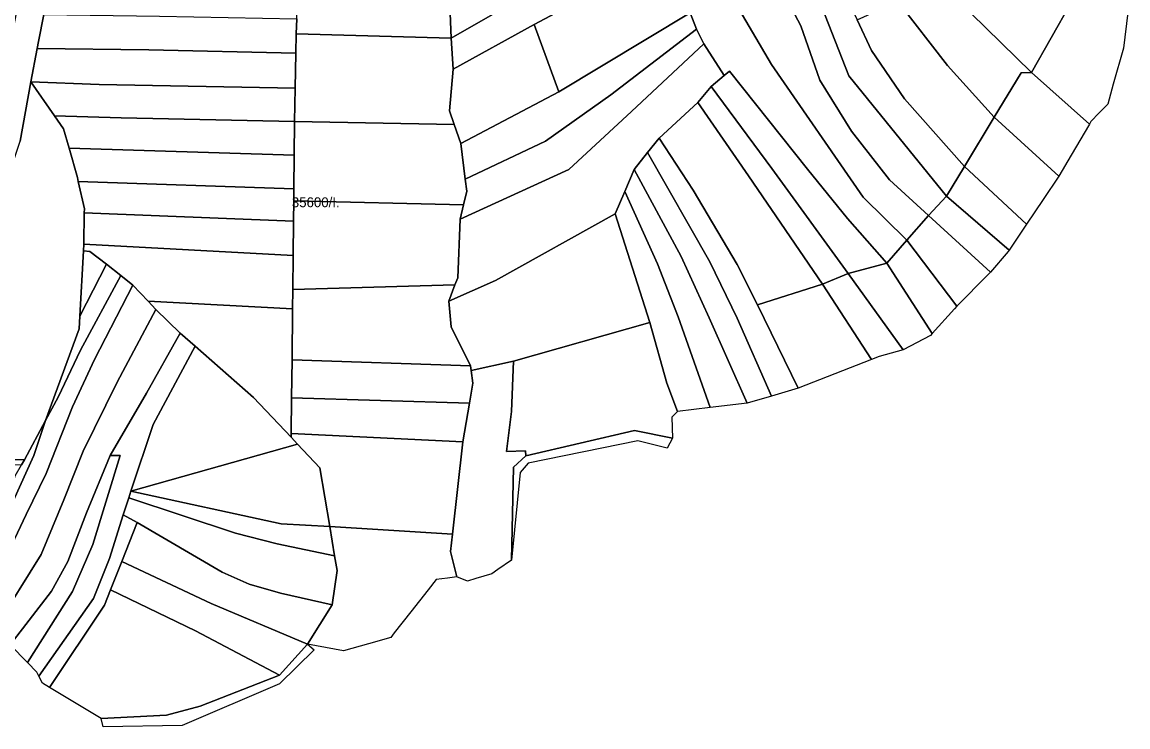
# Model space of a CAD drawing. Extents: x -537068 to -534056, y -1176840 to -1172401.
# Drawn here: x -534697 to -534139, y -1175857 to -1175501 of the extents above; entities that cross this region are included whole.
import ezdxf

# ---------------------------------------------------------------- set-up
doc = ezdxf.new("R2010")
doc.units = 0
for name, color, linetype in [('95610013', 7, 'Continuous'), ('95630013', 7, 'Continuous'), ('95640013', 7, 'Continuous'), ('95660013', 7, 'Continuous')]:
    doc.layers.add(name, color=color, linetype=linetype)

msp = doc.modelspace()

# ---------------------------------------------------------------- linework, layer by layer
at = {"layer": '95610013'}
for points in [[(-534309.1, -1175429), (-534275.74, -1175499.62), (-534268.45, -1175515.14), (-534251.84, -1175539.54), (-534221.44, -1175573.84), (-534230.56, -1175588.8), (-534279.95, -1175527.98), (-534291.85, -1175497.5), (-534332.21, -1175416.26), (-534322.8, -1175410), (-534316.7, -1175408.3)], [(-534291.85, -1175497.5), (-534279.95, -1175527.98), (-534230.56, -1175588.8), (-534239.67, -1175598.58), (-534259.46, -1175580.46), (-534278.62, -1175555.92), (-534294.61, -1175530.11), (-534304.14, -1175502.62), (-534318.85, -1175474.84), (-534348.4, -1175423.92), (-534341.07, -1175419), (-534338.93, -1175418.34), (-534332.21, -1175416.26)], [(-534318.85, -1175474.84), (-534304.14, -1175502.62), (-534294.61, -1175530.11), (-534278.62, -1175555.92), (-534259.46, -1175580.46), (-534239.67, -1175598.58), (-534250.58, -1175610.99), (-534272.76, -1175589.26), (-534319.03, -1175522.16), (-534368.68, -1175437.51), (-534354.54, -1175428.03), (-534348.4, -1175423.92)], [(-534280.66, -1175600.07), (-534300.74, -1175575.06), (-534340.21, -1175525.59), (-534342.87, -1175527.85), (-534353.09, -1175511.77), (-534356.78, -1175504.45), (-534360.05, -1175496.11), (-534370.47, -1175469.58), (-534373.24, -1175463.28), (-534375.65, -1175457.61), (-534381.21, -1175444.57), (-534368.68, -1175437.51), (-534319.03, -1175522.16), (-534272.76, -1175589.26), (-534250.58, -1175610.99), (-534260.77, -1175622.59)], [(-534418.13, -1175449.79), (-534375.65, -1175457.61), (-534373.24, -1175463.28), (-534413.18, -1175467.24), (-534442.21, -1175486.64), (-534480.69, -1175508.98), (-534481.43, -1175492.13), (-534472.95, -1175480.84), (-534448.92, -1175472.59), (-534443.51, -1175464)], [(-534370.47, -1175469.58), (-534387.33, -1175478.81), (-534410.12, -1175483.84), (-534420.15, -1175492.09), (-534438.86, -1175502.02), (-534479.78, -1175524.55), (-534480.69, -1175508.98), (-534442.21, -1175486.64), (-534413.18, -1175467.24), (-534373.24, -1175463.28)], [(-534558.97, -1175506.8), (-534558.7, -1175499.14), (-534558.16, -1175483.43), (-534557.66, -1175468.79), (-534469.54, -1175469.05), (-534472.95, -1175480.84), (-534481.43, -1175492.13), (-534480.69, -1175508.98)], [(-534438.86, -1175502.02), (-534420.15, -1175492.09), (-534410.12, -1175483.84), (-534387.33, -1175478.81), (-534370.47, -1175469.58), (-534360.05, -1175496.11), (-534426.44, -1175536.12)], [(-534187.7, -1175526.35), (-534192.93, -1175526.44), (-534206.45, -1175548.92), (-534230.13, -1175522.7), (-534255.21, -1175490.47), (-534233.61, -1175481.15)], [(-534167.8, -1175491.2), (-534187.7, -1175526.35), (-534233.61, -1175481.15)], [(-534230.13, -1175522.7), (-534206.45, -1175548.92), (-534221.44, -1175573.84), (-534251.84, -1175539.54), (-534268.45, -1175515.14), (-534275.74, -1175499.62), (-534255.21, -1175490.47)], [(-534153.54, -1175546.74), (-534157.7, -1175551.1), (-534158.46, -1175552.4), (-534187.7, -1175526.35), (-534167.8, -1175491.2), (-534139, -1175495.9), (-534141.2, -1175514), (-534146.36, -1175532.18), (-534149.2, -1175542.2)], [(-534628.15, -1175497.81), (-534558.7, -1175499.14), (-534558.97, -1175506.8), (-534559.18, -1175516.47), (-534633.48, -1175514.87), (-534689.8, -1175514.09), (-534689.12, -1175510.64), (-534686.46, -1175497.02)], [(-534360.05, -1175496.11), (-534356.78, -1175504.45), (-534400.15, -1175537.48), (-534433.16, -1175560.94), (-534473.65, -1175580.18), (-534475.88, -1175562.23), (-534426.44, -1175536.12)], [(-534479.78, -1175524.55), (-534438.86, -1175502.02), (-534426.44, -1175536.12), (-534475.88, -1175562.23), (-534479.28, -1175552.53), (-534481.69, -1175545.66)], [(-534479.28, -1175552.53), (-534559.92, -1175550.98), (-534559.56, -1175534.15), (-534559.18, -1175516.47), (-534558.97, -1175506.8), (-534480.69, -1175508.98), (-534479.78, -1175524.55), (-534481.69, -1175545.66)], [(-534476.22, -1175600.36), (-534474.53, -1175593.19), (-534472.89, -1175586.26), (-534473.65, -1175580.18), (-534433.16, -1175560.94), (-534400.15, -1175537.48), (-534356.78, -1175504.45), (-534353.09, -1175511.77), (-534389.63, -1175546.06), (-534421.28, -1175575.21)], [(-534689.8, -1175514.09), (-534633.48, -1175514.87), (-534559.18, -1175516.47), (-534559.56, -1175534.15), (-534658.46, -1175532.4), (-534693.13, -1175530.98)], [(-534349.41, -1175533.39), (-534356.26, -1175541.48), (-534375.8, -1175559.41), (-534381.53, -1175566.7), (-534388.31, -1175575.32), (-534393.11, -1175586.43), (-534397.98, -1175597.72), (-534458.36, -1175631.34), (-534481.97, -1175641.83), (-534478.84, -1175633.55), (-534477.48, -1175629.96), (-534476.22, -1175600.36), (-534421.28, -1175575.21), (-534389.63, -1175546.06), (-534353.09, -1175511.77), (-534342.87, -1175527.85)], [(-534349.41, -1175533.39), (-534342.87, -1175527.85), (-534340.21, -1175525.59), (-534300.74, -1175575.06), (-534280.66, -1175600.07), (-534260.77, -1175622.59), (-534280.32, -1175627.86), (-534318.8, -1175574.83)], [(-534750.52, -1175688.37), (-534735.93, -1175659.99), (-534729.02, -1175644.76), (-534723.65, -1175632.94), (-534712.33, -1175602.64), (-534698.48, -1175560.95), (-534693.13, -1175530.98), (-534681.17, -1175548.21), (-534676.6, -1175554.8), (-534673.77, -1175564.57), (-534669.5, -1175579.3), (-534669.07, -1175581.27), (-534666, -1175595.2), (-534666.04, -1175597.21), (-534666.34, -1175612.96), (-534666.4, -1175616.4), (-534668.32, -1175649.36), (-534668.7, -1175655.8), (-534685.7, -1175702.1), (-534696.3, -1175721.9), (-534728.7, -1175721.7), (-534765.6, -1175721.8), (-534770.72, -1175721.95)], [(-534658.46, -1175532.4), (-534559.56, -1175534.15), (-534559.92, -1175550.98), (-534647.42, -1175549.16), (-534681.17, -1175548.21), (-534693.13, -1175530.98)], [(-534187.7, -1175526.35), (-534158.46, -1175552.4), (-534167.66, -1175568.11), (-534173.8, -1175578.6), (-534206.45, -1175548.92), (-534192.93, -1175526.44)], [(-534318.8, -1175574.83), (-534280.32, -1175627.86), (-534293.28, -1175633.25), (-534330.65, -1175578.48), (-534356.26, -1175541.48), (-534349.41, -1175533.39)], [(-534358.58, -1175585.77), (-534375.8, -1175559.41), (-534356.26, -1175541.48), (-534330.65, -1175578.48), (-534293.28, -1175633.25), (-534326.14, -1175643.61), (-534336.29, -1175623.32)], [(-534647.42, -1175549.16), (-534559.92, -1175550.98), (-534560.07, -1175568.02), (-534673.77, -1175564.57), (-534676.6, -1175554.8), (-534681.17, -1175548.21)], [(-534475.88, -1175562.23), (-534473.65, -1175580.18), (-534472.89, -1175586.26), (-534474.53, -1175593.19), (-534560.27, -1175591.13), (-534560.22, -1175585.07), (-534560.07, -1175568.02), (-534559.92, -1175550.98), (-534479.28, -1175552.53)], [(-534206.45, -1175548.92), (-534173.8, -1175578.6), (-534181.8, -1175590.5), (-534190.18, -1175602.95), (-534221.44, -1175573.84)], [(-534350.08, -1175621.95), (-534381.53, -1175566.7), (-534375.8, -1175559.41), (-534358.58, -1175585.77), (-534336.29, -1175623.32), (-534326.14, -1175643.61), (-534305.6, -1175685.8), (-534318.93, -1175689.74), (-534336.26, -1175650.45)], [(-534669.5, -1175579.3), (-534673.77, -1175564.57), (-534560.07, -1175568.02), (-534560.22, -1175585.07), (-534669.07, -1175581.27)], [(-534388.31, -1175575.32), (-534381.53, -1175566.7), (-534350.08, -1175621.95), (-534336.26, -1175650.45), (-534318.93, -1175689.74), (-534331.3, -1175693.4), (-534350.54, -1175650.22), (-534364.59, -1175619.16)], [(-534388.31, -1175575.32), (-534364.59, -1175619.16), (-534350.54, -1175650.22), (-534331.3, -1175693.4), (-534349.97, -1175695.58), (-534366.16, -1175649.8), (-534376.61, -1175622.9), (-534393.11, -1175586.43)], [(-534198.95, -1175615.99), (-534230.56, -1175588.8), (-534221.44, -1175573.84), (-534190.18, -1175602.95)], [(-534560.22, -1175585.07), (-534560.27, -1175591.13), (-534560.38, -1175601.33), (-534666.04, -1175597.21), (-534666, -1175595.2), (-534669.07, -1175581.27)], [(-534349.97, -1175695.58), (-534366.4, -1175697.5), (-534371.8, -1175683.25), (-534380.43, -1175652.52), (-534397.98, -1175597.72), (-534393.11, -1175586.43), (-534376.61, -1175622.9), (-534366.16, -1175649.8)], [(-534560.27, -1175591.13), (-534474.53, -1175593.19), (-534476.22, -1175600.36), (-534477.48, -1175629.96), (-534478.84, -1175633.55), (-534560.75, -1175635.86), (-534560.57, -1175618.77), (-534560.38, -1175601.33)], [(-534199.5, -1175616.8), (-534208.45, -1175627.18), (-534239.67, -1175598.58), (-534230.56, -1175588.8), (-534198.95, -1175615.99)], [(-534666.04, -1175597.21), (-534560.38, -1175601.33), (-534560.57, -1175618.77), (-534666.34, -1175612.96)], [(-534470.92, -1175674.4), (-534480.78, -1175654.79), (-534481.97, -1175641.83), (-534458.36, -1175631.34), (-534397.98, -1175597.72), (-534380.43, -1175652.52), (-534449.28, -1175672.05), (-534470.61, -1175676.91)], [(-534250.58, -1175610.99), (-534239.67, -1175598.58), (-534208.45, -1175627.18), (-534209.5, -1175628.4), (-534225.33, -1175644.42)], [(-534663.21, -1175616.65), (-534666.4, -1175616.4), (-534666.34, -1175612.96), (-534560.57, -1175618.77), (-534560.75, -1175635.86), (-534560.86, -1175645.69), (-534633.82, -1175641.88), (-534641.45, -1175633.76), (-534647.62, -1175628.85), (-534654.76, -1175623.11)], [(-534260.77, -1175622.59), (-534250.58, -1175610.99), (-534225.33, -1175644.42), (-534226.6, -1175645.7), (-534237.82, -1175658.12)], [(-534654.76, -1175623.11), (-534668.32, -1175649.36), (-534666.4, -1175616.4), (-534663.21, -1175616.65)], [(-534647.62, -1175628.85), (-534668, -1175666.49), (-534679.16, -1175690.37), (-534685.7, -1175702.1), (-534668.7, -1175655.8), (-534668.32, -1175649.36), (-534654.76, -1175623.11)], [(-534260.77, -1175622.59), (-534237.82, -1175658.12), (-534238.7, -1175659.1), (-534252.5, -1175666.4), (-534280.32, -1175627.86)], [(-534641.45, -1175633.76), (-534660.89, -1175671.25), (-534671.97, -1175695.23), (-534685.28, -1175728.86), (-534695.38, -1175749.53), (-534708.73, -1175777.45), (-534719.09, -1175796.69), (-534725.5, -1175788.39), (-534715.51, -1175771.26), (-534701.94, -1175742.9), (-534691.51, -1175719.79), (-534685.7, -1175702.1), (-534679.16, -1175690.37), (-534668, -1175666.49), (-534647.62, -1175628.85)], [(-534293.28, -1175633.25), (-534280.32, -1175627.86), (-534252.5, -1175666.4), (-534264.6, -1175669.8), (-534268.4, -1175671.28)], [(-534666.58, -1175717.56), (-534676.38, -1175742.12), (-534687.85, -1175769.72), (-534711.11, -1175806.77), (-534712.9, -1175804.7), (-534719.09, -1175796.69), (-534708.73, -1175777.45), (-534695.38, -1175749.53), (-534685.28, -1175728.86), (-534671.97, -1175695.23), (-534660.89, -1175671.25), (-534641.45, -1175633.76), (-534633.82, -1175641.88), (-534629.87, -1175646.08), (-534649.44, -1175682.8)], [(-534561.14, -1175671.49), (-534560.86, -1175645.69), (-534560.75, -1175635.86), (-534478.84, -1175633.55), (-534481.97, -1175641.83), (-534480.78, -1175654.79), (-534470.92, -1175674.4)], [(-534268.4, -1175671.28), (-534305.6, -1175685.8), (-534326.14, -1175643.61), (-534293.28, -1175633.25)], [(-534610.02, -1175664.58), (-534617.62, -1175657.91), (-534629.87, -1175646.08), (-534633.82, -1175641.88), (-534560.86, -1175645.69), (-534561.14, -1175671.49), (-534561.34, -1175690.6), (-534561.54, -1175708.73), (-534561.56, -1175710.6), (-534580.53, -1175690.49)], [(-534674.43, -1175773.31), (-534682.62, -1175788.25), (-534703.42, -1175815.43), (-534705.1, -1175813.7), (-534711.11, -1175806.77), (-534687.85, -1175769.72), (-534676.38, -1175742.12), (-534666.58, -1175717.56), (-534649.44, -1175682.8), (-534629.87, -1175646.08), (-534617.62, -1175657.91), (-534634.58, -1175688.25), (-534652.9, -1175719.72), (-534665, -1175748.82)], [(-534369, -1175711), (-534388.2, -1175707.2), (-534443.1, -1175719.9), (-534443.15, -1175717.42), (-534452.83, -1175717.79), (-534450.3, -1175697.57), (-534449.28, -1175672.05), (-534380.43, -1175652.52), (-534371.8, -1175683.25), (-534366.4, -1175697.5), (-534369.4, -1175700.5)], [(-534653.25, -1175771.82), (-534661.46, -1175791.95), (-534688.94, -1175831.32), (-534690, -1175829.2), (-534694.65, -1175824.42), (-534672.04, -1175788.51), (-534661.73, -1175764.74), (-534647.87, -1175719.77), (-534652.9, -1175719.72), (-534634.58, -1175688.25), (-534617.62, -1175657.91), (-534610.02, -1175664.58), (-534631.31, -1175704.11), (-534642.49, -1175737.82), (-534643.6, -1175741.18), (-534646.45, -1175749.76)], [(-534631.31, -1175704.11), (-534610.02, -1175664.58), (-534580.53, -1175690.49), (-534561.56, -1175710.6), (-534558.34, -1175714.01), (-534642.49, -1175737.82)], [(-534470.92, -1175674.4), (-534470.61, -1175676.91), (-534469.84, -1175683.23), (-534471.54, -1175693.42), (-534561.34, -1175690.6), (-534561.14, -1175671.49)], [(-534474.79, -1175712.83), (-534471.54, -1175693.42), (-534469.84, -1175683.23), (-534470.61, -1175676.91), (-534449.28, -1175672.05), (-534450.3, -1175697.57), (-534452.83, -1175717.79), (-534443.15, -1175717.42), (-534443.1, -1175719.9), (-534449.3, -1175725.6), (-534450.3, -1175772.6), (-534457.22, -1175777.42), (-534460.2, -1175779.5), (-534468.27, -1175781.97), (-534472.6, -1175783.3), (-534477.9, -1175781.1), (-534481.1, -1175768.37), (-534480.09, -1175759.48)], [(-534561.54, -1175708.73), (-534561.34, -1175690.6), (-534471.54, -1175693.42), (-534474.79, -1175712.83)], [(-534697.8, -1175724.5), (-534696.3, -1175721.9), (-534685.7, -1175702.1), (-534691.51, -1175719.79), (-534701.94, -1175742.9), (-534715.51, -1175771.26), (-534725.5, -1175788.39), (-534734.3, -1175777), (-534721.9, -1175766.7), (-534703.6, -1175742), (-534700.9, -1175730.1)], [(-534480.09, -1175759.48), (-534542.1, -1175755.58), (-534547.02, -1175726.02), (-534558.34, -1175714.01), (-534561.56, -1175710.6), (-534561.54, -1175708.73), (-534474.79, -1175712.83)], [(-534443.1, -1175719.9), (-534388.2, -1175707.2), (-534369, -1175711), (-534371.7, -1175716), (-534386.5, -1175712.3), (-534441.8, -1175723.6), (-534446, -1175728.4), (-534450.3, -1175772.6), (-534449.3, -1175725.6)], [(-534542.1, -1175755.58), (-534566.61, -1175754.34), (-534642.49, -1175737.82), (-534558.34, -1175714.01), (-534547.02, -1175726.02)], [(-534672.04, -1175788.51), (-534694.65, -1175824.42), (-534703.42, -1175815.43), (-534682.62, -1175788.25), (-534674.43, -1175773.31), (-534665, -1175748.82), (-534652.9, -1175719.72), (-534647.87, -1175719.77), (-534661.73, -1175764.74)], [(-534568.62, -1175764.4), (-534589.64, -1175759.01), (-534643.6, -1175741.18), (-534642.49, -1175737.82), (-534566.61, -1175754.34), (-534542.1, -1175755.58), (-534539.63, -1175770.42)], [(-534582.77, -1175784.86), (-534596.44, -1175778.79), (-534639.31, -1175753.57), (-534646.45, -1175749.76), (-534643.6, -1175741.18), (-534589.64, -1175759.01), (-534568.62, -1175764.4), (-534539.63, -1175770.42), (-534538.39, -1175777.85), (-534540.85, -1175795.21), (-534567.03, -1175789.29)], [(-534639.31, -1175753.57), (-534647.11, -1175773.34), (-534652.76, -1175787.67), (-534655.85, -1175795.42), (-534683.7, -1175836.92), (-534687.2, -1175834.8), (-534688.94, -1175831.32), (-534661.46, -1175791.95), (-534653.25, -1175771.82), (-534646.45, -1175749.76)], [(-534639.31, -1175753.57), (-534596.44, -1175778.79), (-534582.77, -1175784.86), (-534567.03, -1175789.29), (-534540.85, -1175795.21), (-534553.3, -1175815.1), (-534602.05, -1175794.52), (-534647.11, -1175773.34)], [(-534480.09, -1175759.48), (-534481.1, -1175768.37), (-534477.9, -1175781.1), (-534482.68, -1175781.7), (-534488.3, -1175782.4), (-534492.38, -1175787.6), (-534501.15, -1175798.77), (-534509.48, -1175809.38), (-534511.3, -1175811.7), (-534522.47, -1175814.89), (-534535.1, -1175818.5), (-534553.3, -1175815.1), (-534540.85, -1175795.21), (-534538.39, -1175777.85), (-534539.63, -1175770.42), (-534542.1, -1175755.58)], [(-534567.5, -1175830.7), (-534609.84, -1175808.4), (-534652.76, -1175787.67), (-534647.11, -1175773.34), (-534602.05, -1175794.52), (-534553.3, -1175815.1)], [(-534607.5, -1175846.5), (-534624.5, -1175850.9), (-534657.6, -1175852.7), (-534683.7, -1175836.92), (-534655.85, -1175795.42), (-534652.76, -1175787.67), (-534609.84, -1175808.4), (-534567.5, -1175830.7)]]:
    msp.add_lwpolyline(points, close=True, dxfattribs=at)
at = {"layer": '95630013'}
msp.add_lwpolyline([(-534702.48, -1175507.7), (-534690.12, -1175443.5), (-534679.46, -1175398.47), (-534670.16, -1175373.86), (-534659.8, -1175351.9), (-534652.46, -1175352.81), (-534650.83, -1175353.01), (-534643.48, -1175353.92), (-534646.77, -1175360.91), (-534652.96, -1175374.04), (-534658.28, -1175388.31), (-534663.25, -1175401.65), (-534663.85, -1175403.25), (-534668.17, -1175417.92), (-534672.73, -1175433.39), (-534676.59, -1175446.48), (-534677.11, -1175449.15), (-534680.17, -1175464.82), (-534683.27, -1175480.7), (-534686.46, -1175497.02), (-534689.12, -1175510.64), (-534689.8, -1175514.09), (-534693.13, -1175530.98), (-534698.48, -1175560.95)], dxfattribs=at)
at = {"layer": '95640013'}
for points in [[(-534696.3, -1175721.9), (-534697.8, -1175724.5), (-534728.9, -1175725.2), (-534765, -1175725.6), (-534769.2, -1175728.4), (-534770.72, -1175721.95), (-534765.6, -1175721.8), (-534728.7, -1175721.7)], [(-534616.7, -1175856.2), (-534656.5, -1175856.9), (-534657.6, -1175852.7), (-534624.5, -1175850.9), (-534607.5, -1175846.5), (-534567.5, -1175830.7), (-534553.3, -1175815.1), (-534549.9, -1175818), (-534567.5, -1175835.2)]]:
    msp.add_lwpolyline(points, close=True, dxfattribs=at)
at = {"layer": '95660013'}
msp.add_lwpolyline([(-534139, -1175495.9), (-534141.2, -1175514), (-534146.36, -1175532.18), (-534149.2, -1175542.2), (-534153.54, -1175546.74), (-534157.7, -1175551.1), (-534158.46, -1175552.4), (-534167.66, -1175568.11), (-534173.8, -1175578.6), (-534181.8, -1175590.5), (-534190.18, -1175602.95), (-534198.95, -1175615.99), (-534199.5, -1175616.8), (-534208.45, -1175627.18), (-534209.5, -1175628.4), (-534225.33, -1175644.42), (-534226.6, -1175645.7), (-534237.82, -1175658.12), (-534238.7, -1175659.1), (-534252.5, -1175666.4), (-534264.6, -1175669.8), (-534268.4, -1175671.28), (-534305.6, -1175685.8), (-534318.93, -1175689.74), (-534331.3, -1175693.4), (-534349.97, -1175695.58), (-534366.4, -1175697.5), (-534369.4, -1175700.5), (-534369, -1175711), (-534371.7, -1175716), (-534386.5, -1175712.3), (-534441.8, -1175723.6), (-534446, -1175728.4), (-534450.3, -1175772.6), (-534457.22, -1175777.42), (-534460.2, -1175779.5), (-534468.27, -1175781.97), (-534472.6, -1175783.3), (-534477.9, -1175781.1), (-534482.68, -1175781.7), (-534488.3, -1175782.4), (-534492.38, -1175787.6), (-534501.15, -1175798.77), (-534509.48, -1175809.38), (-534511.3, -1175811.7), (-534522.47, -1175814.89), (-534535.1, -1175818.5), (-534553.3, -1175815.1), (-534549.9, -1175818), (-534567.5, -1175835.2), (-534616.7, -1175856.2), (-534656.5, -1175856.9), (-534657.6, -1175852.7), (-534683.7, -1175836.92), (-534687.2, -1175834.8), (-534688.94, -1175831.32), (-534690, -1175829.2), (-534694.65, -1175824.42), (-534703.42, -1175815.43)], dxfattribs=at)

# ---------------------------------------------------------------- texts
msp.add_text('35600/I.', height=5, rotation=0, dxfattribs=at).set_placement((-534561.24, -1175594.34))

doc.saveas('drawing.dxf')
